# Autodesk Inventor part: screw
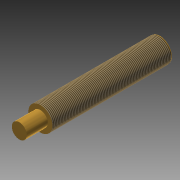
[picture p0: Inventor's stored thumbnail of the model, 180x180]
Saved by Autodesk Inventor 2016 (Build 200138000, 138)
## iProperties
Created: 2014-12
Part Number: screw
Material: Generic
Document SubType Name: Modeling
Designer: James
Density: 1 g/cm^3
Appearance: Brass - Satin
Author: James
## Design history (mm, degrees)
sketch "Sketch1"
  geometry: C1 r 4 at (0, 0); 2 further points
  constraints: 2 coincident, 1 centre point
  dimensions: "d0" = 8 diameter of C1
extrude "Extrusion1" new body sketch "Sketch1" distance "d1" = 40; taper "d2" = 0 deg
thread "Thread1" dims "d3" = 33, "d4" = 0
sketch "Sketch2"
  geometry: C1 r 4 at (0, 0) reference; C2 r 2.5 at (0, 0)
  constraints: 1 centre point, 1 coincident
  dimensions: "d5" = 5 diameter of C2
extrude "Extrusion2" cut sketch "Sketch2" distance "d6" = 2.5; taper "d7" = 0 deg
fillet "Fillet1" dims "d8" = 2.5
fillet "Fillet2" dims "d9" = 0.5
sketch "Sketch4"
  geometry: C1 r 2.5 at (0, 0); 1 further point
  constraints: 1 centre point, 1 coincident
  dimensions: "d13" = 5 diameter of C1
extrude "Extrusion4" join sketch "Sketch4" distance "d14" = 7; taper "d15" = 0 deg
body "Solid1"
